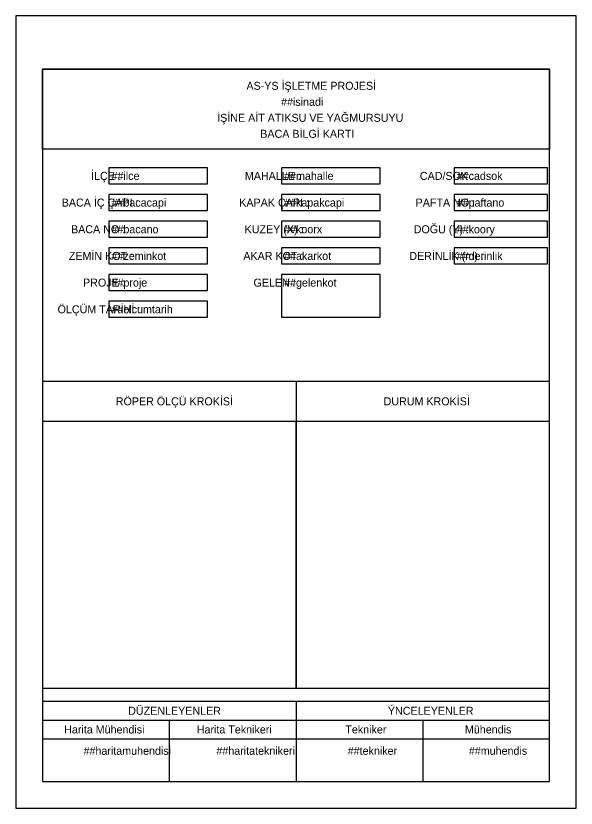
# Model space of a CAD drawing. Extents: x 0 to 210, y 0 to 297.
import ezdxf

# ---------------------------------------------------------------- set-up
doc = ezdxf.new("R2010")
doc.units = 0
for name, color, linetype in [('bbk_baslik', 7, 'Continuous'), ('bbk_cerceve_1', 7, 'Continuous'), ('bbk_cerceve_2', 7, 'Continuous'), ('bbk_kroki_1', 7, 'Continuous'), ('bbk_kroki_2', 7, 'Continuous')]:
    doc.layers.add(name, color=color, linetype=linetype)

msp = doc.modelspace()

# ---------------------------------------------------------------- linework, layer by layer
at = {"layer": 'bbk_cerceve_1'}
msp.add_lwpolyline([(0, 0), (210, 0), (210, 297), (0, 297)], close=True, dxfattribs=at)
at = {"layer": 'bbk_cerceve_2'}
for p, q in [((10, 160), (200, 160)), ((105, 160), (105, 145)), ((105, 40), (105, 10)), ((10, 33), (105, 33)), ((57.5, 33), (57.5, 10)), ((105, 33), (200, 33)), ((152.5, 33), (152.5, 10)), ((10, 26), (105, 26)), ((105, 26), (200, 26))]:
    msp.add_line(p, q, dxfattribs=at)
for points in [[(10, 10), (200, 10), (200, 277), (10, 277)], [(10, 277), (200, 277), (200, 247), (10, 247)], [(34.85, 234), (71.85, 234), (71.85, 240), (34.85, 240)], [(99.54, 234), (136.54, 234), (136.54, 240), (99.54, 240)], [(164.23, 234), (199.23, 234), (199.23, 240), (164.23, 240)], [(34.85, 224), (71.85, 224), (71.85, 230), (34.85, 230)], [(99.54, 224), (136.54, 224), (136.54, 230), (99.54, 230)], [(164.23, 224), (199.23, 224), (199.23, 230), (164.23, 230)], [(34.85, 214), (71.85, 214), (71.85, 220), (34.85, 220)], [(99.54, 214), (136.54, 214), (136.54, 220), (99.54, 220)], [(164.23, 214), (199.23, 214), (199.23, 220), (164.23, 220)], [(34.85, 204), (71.85, 204), (71.85, 210), (34.85, 210)], [(99.54, 204), (136.54, 204), (136.54, 210), (99.54, 210)], [(164.23, 204), (199.23, 204), (199.23, 210), (164.23, 210)], [(34.85, 194), (71.85, 194), (71.85, 200), (34.85, 200)], [(99.54, 184), (136.54, 184), (136.54, 200), (99.54, 200)], [(34.85, 184), (71.85, 184), (71.85, 190), (34.85, 190)], [(10, 10), (200, 10), (200, 40), (10, 40)]]:
    msp.add_lwpolyline(points, close=True, dxfattribs=at)
at = {"layer": 'bbk_kroki_1'}
msp.add_lwpolyline([(10, 45), (105, 45), (105, 145), (10, 145)], close=True, dxfattribs=at)
at = {"layer": 'bbk_kroki_2'}
msp.add_lwpolyline([(105, 45), (200, 45), (200, 145), (105, 145)], close=True, dxfattribs=at)

# ---------------------------------------------------------------- texts
at = {"layer": 'bbk_baslik'}
for s, p in [('AS-YS İŞLETME PROJESİ', (86.43, 269.28)), ('##isinadi', (99.4, 263.28)), ('İŞİNE AİT ATIKSU VE YAĞMURSUYU', (75.46, 257.28)), ('BACA BİLGİ KARTI', (91.61, 251.28)), ('İLÇE :', (28.19, 235.5)), ('##ilce', (35.85, 235.5)), ('MAHALLE :', (85.85, 235.5)), ('##mahalle', (100.54, 235.5)), ('CAD/SOK :', (151.42, 235.5)), ('##cadsok', (165.23, 235.5)), ('BACA İÇ ÇAPI :', (17.2, 225.5)), ('##bacacapi', (35.85, 225.5)), ('KAPAK ÇAPI :', (83.74, 225.5)), ('##kapakcapi', (100.54, 225.5)), ('PAFTA NO :', (149.83, 225.5)), ('##paftano', (165.23, 225.5)), ('BACA NO :', (20.69, 215.5)), ('##bacano', (35.85, 215.5)), ('KUZEY (X) :', (85.74, 215.5)), ('##koorx', (100.54, 215.5)), ('DOĞU (Y) :', (149.12, 215.5)), ('##koory', (165.23, 215.5)), ('ZEMİN KOT :', (19.85, 205.5)), ('##zeminkot', (35.85, 205.5)), ('AKAR KOT :', (85.26, 205.5)), ('##akarkot', (100.54, 205.5)), ('DERİNLİK (m) :', (147.47, 205.5)), ('##derinlik', (165.23, 205.5)), ('PROJE :', (25.19, 195.5)), ('##proje', (35.85, 195.5)), ('GELEN :', (89.07, 195.5)), ('##gelenkot', (100.54, 195.5)), ('ÖLÇÜM TARİHİ :', (15.65, 185.5)), ('##olcumtarih', (35.85, 185.5)), ('RÖPER ÖLÇÜ KROKİSİ', (37.46, 151)), ('DURUM KROKİSİ', (137.83, 151)), ('DÜZENLEYENLER', (42.1, 35)), ('ÝNCELEYENLER', (139.44, 35)), ('Harita Mühendisi', (18.12, 28)), ('Harita Teknikeri', (67.81, 28)), ('Tekniker', (123.49, 28)), ('Mühendis', (168.32, 28)), ('##haritamuhendisi', (25.38, 20)), ('##haritateknikeri', (75.16, 20)), ('##tekniker', (124.39, 20)), ('##muhendis', (169.79, 20))]:
    msp.add_text(s, height=3, dxfattribs=at).set_placement(p)

doc.saveas('drawing.dxf')
